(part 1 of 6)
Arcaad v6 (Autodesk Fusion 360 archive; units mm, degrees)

design "Arcaad" references "Joystick assembly", "Untitled", "Arcade_Box"
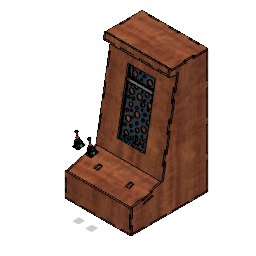
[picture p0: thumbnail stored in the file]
parameter "th" = 12
parameter "bl" = 480
parameter "bw" = 220
parameter "dbToolDia" = 6.35
parameter "dbOffset" = 0 comment "Do NOT change formula"
parameter "dbRadius" = 3.175 (= "( dbToolDia + dbOffset ) / 2") comment "Do NOT change formula"
parameter "dbHoleOffset" = 2.2451 (= "dbRadius / sqrt(2)") comment "Do NOT change formula"
component_insert "Component Insert1"
position "Position1"
sketch "Sketch1" plane through (0, 0, -312.3436) normal (0, 0, -1) x axis (-1, 0, 0)
  line L1 (205, -584.2019) -> (205, -596.2019)
  line L2 (300, -584.2019) -> (205, -584.2019)
  line L3 (300, -378.4667) -> (300, -584.2019)
  line L4 (294, -378.4667) -> (300, -378.4667)
  line L5 (294, -393.4667) -> (294, -378.4667)
  line L6 (288, -393.4667) -> (294, -393.4667)
  line L7 (288, -313.4667) -> (288, -393.4667)
  line L8 (294, -313.4667) -> (288, -313.4667)
  line L9 (294, -328.4667) -> (294, -313.4667)
  line L10 (300, -328.4667) -> (294, -328.4667)
  line L11 (300, -128.4667) -> (300, -328.4667)
  line L12 (294, -128.4667) -> (300, -128.4667)
  line L13 (294, -143.4667) -> (294, -128.4667)
  line L14 (288, -143.4667) -> (294, -143.4667)
  line L15 (288, -63.4667) -> (288, -143.4667)
  line L16 (294, -63.4667) -> (288, -63.4667)
  line L17 (294, -78.4667) -> (294, -63.4667)
  line L18 (300, -78.4667) -> (294, -78.4667)
  line L19 (300, 121.5333) -> (300, -78.4667)
  line L20 (294, 121.5333) -> (300, 121.5333)
  line L21 (294, 106.5333) -> (294, 121.5333)
  line L22 (288, 106.5333) -> (294, 106.5333)
  line L23 (288, 186.5333) -> (288, 106.5333)
  line L24 (294, 186.5333) -> (288, 186.5333)
  line L25 (294, 171.5333) -> (294, 186.5333)
  line L26 (300, 171.5333) -> (294, 171.5333)
  line L27 (300, 377.2686) -> (300, 171.5333)
  line L28 (205, 377.2686) -> (300, 377.2686)
  line L29 (205, 389.2686) -> (205, 377.2686)
  line L30 (155, 389.2686) -> (205, 389.2686)
  line L31 (155, 377.2686) -> (155, 389.2686)
  line L32 (25, 377.2686) -> (155, 377.2686)
  line L33 (25, 389.2686) -> (25, 377.2686)
  line L34 (-25, 389.2686) -> (25, 389.2686)
  line L35 (-25, 377.2686) -> (-25, 389.2686)
  line L36 (-155, 377.2686) -> (-25, 377.2686)
  line L37 (-155, 389.2686) -> (-155, 377.2686)
  line L38 (-205, 389.2686) -> (-155, 389.2686)
  line L39 (-205, 377.2686) -> (-205, 389.2686)
  line L40 (-300, 377.2686) -> (-205, 377.2686)
  line L41 (-300, 171.5333) -> (-300, 377.2686)
  line L42 (-294, 171.5333) -> (-300, 171.5333)
  line L43 (-294, 186.5333) -> (-294, 171.5333)
  line L44 (-288, 186.5333) -> (-294, 186.5333)
  line L45 (-288, 106.5333) -> (-288, 186.5333)
  line L46 (-294, 106.5333) -> (-288, 106.5333)
  line L47 (-294, 121.5333) -> (-294, 106.5333)
  line L48 (-300, 121.5333) -> (-294, 121.5333)
  line L49 (-300, -78.4667) -> (-300, 121.5333)
  line L50 (-294, -78.4667) -> (-300, -78.4667)
  line L51 (-294, -63.4667) -> (-294, -78.4667)
  line L52 (-288, -63.4667) -> (-294, -63.4667)
  line L53 (-288, -143.4667) -> (-288, -63.4667)
  line L54 (-294, -143.4667) -> (-288, -143.4667)
  line L55 (-294, -128.4667) -> (-294, -143.4667)
  line L56 (-300, -128.4667) -> (-294, -128.4667)
  line L57 (-300, -328.4667) -> (-300, -128.4667)
  line L58 (-294, -328.4667) -> (-300, -328.4667)
  line L59 (-294, -313.4667) -> (-294, -328.4667)
  line L60 (-288, -313.4667) -> (-294, -313.4667)
  line L61 (-288, -393.4667) -> (-288, -313.4667)
  line L62 (-294, -393.4667) -> (-288, -393.4667)
  line L63 (-294, -378.4667) -> (-294, -393.4667)
  line L64 (-300, -378.4667) -> (-294, -378.4667)
  line L65 (-300, -584.2019) -> (-300, -378.4667)
  line L66 (-205, -584.2019) -> (-300, -584.2019)
  line L67 (-205, -596.2019) -> (-205, -584.2019)
  line L68 (-155, -596.2019) -> (-205, -596.2019)
  line L69 (-155, -584.2019) -> (-155, -596.2019)
  line L70 (-25, -584.2019) -> (-155, -584.2019)
  line L71 (-25, -596.2019) -> (-25, -584.2019)
  line L72 (25, -596.2019) -> (-25, -596.2019)
  line L73 (25, -584.2019) -> (25, -596.2019)
  line L74 (155, -584.2019) -> (25, -584.2019)
  line L75 (155, -596.2019) -> (155, -584.2019)
  line L76 (205, -596.2019) -> (155, -596.2019)
  line L77 (205, 389.2686) -> (300, 389.2686)
  line L78 (205, 377.2686) -> (205, 389.2686)
  line L79 (300, 377.2686) -> (205, 377.2686)
  line L80 (300, 389.2686) -> (300, 377.2686)
  line L81 (25, 389.2686) -> (155, 389.2686)
  line L82 (-155, 389.2686) -> (-25, 389.2686)
  line L83 (-155, 377.2686) -> (-155, 389.2686)
  line L84 (-25, 377.2686) -> (-155, 377.2686)
  line L85 (-25, 389.2686) -> (-25, 377.2686)
  line L86 (-300, 389.2686) -> (-205, 389.2686)
  line L87 (-300, 377.2686) -> (-300, 389.2686)
  line L88 (-205, 377.2686) -> (-300, 377.2686)
  line L89 (-205, 389.2686) -> (-205, 377.2686)
  line L90 (-224, 171.5333) -> (-218, 171.5333)
  line L91 (-224, 121.5333) -> (-224, 171.5333)
  line L92 (-218, 121.5333) -> (-224, 121.5333)
  line L93 (-218, 106.5333) -> (-218, 121.5333)
  line L94 (-212, 106.5333) -> (-218, 106.5333)
  line L95 (-212, 186.5333) -> (-212, 106.5333)
  line L96 (-218, 186.5333) -> (-212, 186.5333)
  line L97 (-218, 171.5333) -> (-218, 186.5333)
  line L98 (300, 121.5333) -> (294, 121.5333)
  line L99 (300, 171.5333) -> (300, 121.5333)
  line L100 (294, 171.5333) -> (300, 171.5333)
  line L101 (294, 186.5333) -> (294, 171.5333)
  line L102 (288, 186.5333) -> (294, 186.5333)
  line L103 (288, 106.5333) -> (288, 186.5333)
  line L104 (294, 106.5333) -> (288, 106.5333)
  line L105 (294, 121.5333) -> (294, 106.5333)
  line L106 (-224, -78.4667) -> (-218, -78.4667)
  line L107 (-224, -128.4667) -> (-224, -78.4667)
  line L108 (-218, -128.4667) -> (-224, -128.4667)
  line L109 (-218, -143.4667) -> (-218, -128.4667)
  line L110 (-212, -143.4667) -> (-218, -143.4667)
  line L111 (-212, -63.4667) -> (-212, -143.4667)
  line L112 (-218, -63.4667) -> (-212, -63.4667)
  line L113 (-218, -78.4667) -> (-218, -63.4667)
  line L114 (-205, -596.2019) -> (-300, -596.2019)
  line L115 (-205, -584.2019) -> (-205, -596.2019)
  line L116 (-300, -584.2019) -> (-205, -584.2019)
  line L117 (-300, -596.2019) -> (-300, -584.2019)
  line L118 (-25, -596.2019) -> (-155, -596.2019)
  line L119 (-25, -584.2019) -> (-25, -596.2019)
  line L120 (-155, -584.2019) -> (-25, -584.2019)
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  point P135 (300, -596.2019)
  point P166 (300, -596.2019)
  point P159 (-224, -328.4667)
  point P164 (-224, -328.4667)
  point P78 (300, 389.2686)
  point P169 (300, 389.2686)
  coincident P135 P166
  coincident P159 P164
  coincident P78 P169
extrude "Extrude1" new body sketch "Sketch1" to an object
position "Position2"
position "Position3"
combine "Combine1"
sketch "Sketch2" plane through (0, -584.2019, 0) normal (0, -1, 0) x axis (1, 0, 0)
  line L1 (-300, 287.6564) -> (-288, 287.6564)
  line L2 (-300, 193.6564) -> (-300, 287.6564)
  line L3 (-294, 193.6564) -> (-300, 193.6564)
  line L4 (-294, 208.6564) -> (-294, 193.6564)
  line L5 (-288, 208.6564) -> (-294, 208.6564)
  line L6 (-288, 287.6564) -> (-288, 208.6564)
  line L7 (223.5439, 299.6564) -> (-300, 299.6564)
  line L8 (223.5439, -312.3436) -> (223.5439, 299.6564)
  line L9 (-300, -312.3436) -> (223.5439, -312.3436)
  line L10 (-300, 299.6564) -> (-300, -312.3436)
  line L11 (-300, -312.3436) -> (224, -312.3436)
  line L12 (-288, -300.3436) -> (211.5439, -300.3436)
  line L13 (-288, 287.6564) -> (-288, -300.3436)
  line L14 (211.5439, 287.6564) -> (-288, 287.6564)
  line L15 (211.5439, -300.3436) -> (211.5439, 287.6564)
  line L16 (-38, -312.3436) -> (-38.228, 299.6564)
  line L17 (-78, -312.3585) -> (-78.228, 299.6415)
  line L18 (2, -312.3287) -> (1.772, 299.6713)
  line L19 (-13, -312.3343) -> (-13.228, 299.6657)
  line L20 (-63, -312.3529) -> (-63.228, 299.6471)
  line L21 (-223, -312.3529) -> (-223.228, 299.6471)
  line L22 (-238, -312.3585) -> (-238.228, 299.6415)
  line L23 (-173, -312.3343) -> (-173.228, 299.6657)
  line L24 (-158, -312.3287) -> (-158.228, 299.6713)
  line L25 (97, -312.3529) -> (96.772, 299.6471)
  line L26 (82, -312.3585) -> (81.772, 299.6415)
  line L27 (147, -312.3343) -> (146.772, 299.6657)
  line L28 (162, -312.3287) -> (161.772, 299.6713)
  line L29 (-294, -306.3436) -> (217.5439, -306.3436)
  line L30 (-294, 293.6564) -> (-294, -306.3436)
  line L31 (217.5439, 293.6564) -> (-294, 293.6564)
  line L32 (217.5439, -306.3436) -> (217.5439, 293.6564)
  line L33 (224, -312.3436) -> (-300, -312.3436)
  line L34 (-173.0022, -312.3529) -> (-223, -312.3529)
  line L35 (-173.0022, -306.3436) -> (-173.0022, -312.3529)
  line L36 (-223, -306.3436) -> (-173.0022, -306.3436)
  line L37 (-223, -312.3529) -> (-223, -306.3436)
  line L38 (-63.0022, -312.3343) -> (-13, -312.3343)
  line L39 (-63.0022, -306.3436) -> (-63.0022, -312.3343)
  line L40 (-13, -306.3436) -> (-63.0022, -306.3436)
  line L41 (-13, -312.3343) -> (-13, -306.3436)
  line L42 (146.9978, -312.3529) -> (97, -312.3529)
  line L43 (146.9978, -306.3436) -> (146.9978, -312.3529)
  line L44 (97, -306.3436) -> (146.9978, -306.3436)
  line L45 (97, -312.3529) -> (97, -306.3436)
  line L46 (146.772, 293.6564) -> (96.7742, 293.6564)
  line L47 (146.772, 299.6657) -> (146.772, 293.6564)
  line L48 (96.7742, 299.6657) -> (146.772, 299.6657)
  line L49 (96.7742, 293.6564) -> (96.7742, 299.6657)
  line L50 (-13.228, 293.6564) -> (-63.2258, 293.6564)
  line L51 (-13.228, 299.6657) -> (-13.228, 293.6564)
  line L52 (-63.2258, 299.6657) -> (-13.228, 299.6657)
  line L53 (-63.2258, 293.6564) -> (-63.2258, 299.6657)
  line L54 (-173.228, 293.6564) -> (-223.2258, 293.6564)
  line L55 (-173.228, 299.6657) -> (-173.228, 293.6564)
  line L56 (-223.2258, 299.6657) -> (-173.228, 299.6657)
  line L57 (-223.2258, 293.6564) -> (-223.2258, 299.6657)
  point P10 (223.5439, -312.3436)
  point P8 (-300, 299.6564)
  point P12 (-300, 299.6564)
  point P19 (-38.228, 299.6564)
  point P20 (-38, -312.3436)
  point P13 (224, -312.3436)
  point P49 (224, -312.3436)
  point P51 (-173.0022, -306.3436)
  point P54 (-63.0022, -306.3436)
  point P57 (146.9978, -306.3436)
  point P59 (96.7742, 293.6564)
  point P62 (-63.2258, 293.6564)
  point P65 (-223.2258, 293.6564)
  horizontal L7
  vertical L8
  horizontal L9
  vertical L10
  coincident P10 L11
  coincident P8 P12
  midpoint L7 P19
  midpoint L11 P20
  coincident P13 P49
  horizontal L34
  vertical L35
  horizontal L36
  vertical L37
  coincident L29 P51
  coincident L23 P51
  horizontal L38
  vertical L39
  horizontal L40
  vertical L41
  coincident L29 P54
  coincident L20 P54
  horizontal L42
  vertical L43
  horizontal L44
  vertical L45
  coincident L27 P57
  coincident L29 P57
  horizontal L46
  vertical L47
  horizontal L48
  vertical L49
  coincident L31 P59
  coincident L25 P59
  horizontal L50
  vertical L51
  horizontal L52
  vertical L53
  coincident L31 P62
  coincident L20 P62
  horizontal L54
  vertical L55
  horizontal L56
  vertical L57
  coincident L21 P65
  coincident L31 P65
  dimension "d6" = 12
  dimension "d7" = 40
  dimension "d8" = -40
  dimension "d9" = -25
  dimension "d10" = 25
  dimension "d15" = 6
  dimension "d13" R-Pattern1-uDistance = 160
  dimension "d14" R-Pattern1-vDistance = 0
position "Position4"
extrude "Extrude1" new body sketch "Sketch2" profile of L1 L2 L3 L4 L5 L6 L7 L8 L9 L10 L11 L12 L14 L13 L15 L16 L17 L18 L19 L20 L21 L22 L23 L24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 to an object
extrude "Extrude2" cut of existing geometry blind -10
extrude "Extrude3" cut of existing geometry blind -10
extrude "Extrude4" cut of existing geometry blind -13
combine "Combine2"
sketch "Sketch3" plane through (0, -596.2019, 0) normal (0, -1, 0) x axis (1, 0, 0)
  line L1 (-63, -312.3343) -> (-63, -312.3436)
  line L2 (-63.0022, -306.3436) -> (-63, -312.3343)
  line L3 (-78.0022, -306.3436) -> (-63.0022, -306.3436)
  line L4 (-78.0045, -300.3436) -> (-78.0022, -306.3436)
  line L5 (1.9955, -300.3436) -> (-78.0045, -300.3436)
  line L6 (1.9978, -306.3436) -> (1.9955, -300.3436)
  line L7 (-13.0022, -306.3436) -> (1.9978, -306.3436)
  line L8 (-13, -312.3343) -> (-13.0022, -306.3436)
  line L9 (-13, -312.3436) -> (-13, -312.3343)
  line L10 (97, -312.3436) -> (-13, -312.3436)
  line L11 (97, -306.3436) -> (97, -312.3436)
  line L12 (81.9978, -306.3436) -> (97, -306.3436)
  line L13 (81.9955, -300.3436) -> (81.9978, -306.3436)
  line L14 (161.9955, -300.3436) -> (81.9955, -300.3436)
  line L15 (161.9978, -306.3436) -> (161.9955, -300.3436)
  line L16 (146.9978, -306.3436) -> (161.9978, -306.3436)
  line L17 (146.9978, -312.3436) -> (146.9978, -306.3436)
  line L18 (223.5439, -312.3436) -> (146.9978, -312.3436)
  line L19 (223.5439, 299.6564) -> (223.5439, -312.3436)
  line L20 (146.772, 299.6564) -> (223.5439, 299.6564)
  line L21 (146.7742, 293.6564) -> (146.772, 299.6564)
  line L22 (161.7742, 293.6564) -> (146.7742, 293.6564)
  line L23 (161.7764, 287.6564) -> (161.7742, 293.6564)
  line L24 (81.7764, 287.6564) -> (161.7764, 287.6564)
  line L25 (81.7742, 293.6564) -> (81.7764, 287.6564)
  line L26 (96.7742, 293.6564) -> (81.7742, 293.6564)
  line L27 (96.7742, 299.6564) -> (96.7742, 293.6564)
  line L28 (-13.228, 299.6564) -> (96.7742, 299.6564)
  line L29 (-13.228, 293.6564) -> (-13.228, 299.6564)
  line L30 (1.7742, 293.6564) -> (-13.228, 293.6564)
  line L31 (1.7764, 287.6564) -> (1.7742, 293.6564)
  line L32 (-78.2236, 287.6564) -> (1.7764, 287.6564)
  line L33 (-78.2258, 293.6564) -> (-78.2236, 287.6564)
  line L34 (-63.2258, 293.6564) -> (-78.2258, 293.6564)
  line L35 (-63.2258, 299.6564) -> (-63.2258, 293.6564)
  line L36 (-173.228, 299.6564) -> (-63.2258, 299.6564)
  line L37 (-173.228, 293.6564) -> (-173.228, 299.6564)
  line L38 (-158.2258, 293.6564) -> (-173.228, 293.6564)
  line L39 (-158.2236, 287.6564) -> (-158.2258, 293.6564)
  line L40 (-238.2236, 287.6564) -> (-158.2236, 287.6564)
  line L41 (-238.2258, 293.6564) -> (-238.2236, 287.6564)
  line L42 (-223.2258, 293.6564) -> (-238.2258, 293.6564)
  line L43 (-223.2258, 299.6564) -> (-223.2258, 293.6564)
  line L44 (-300, 299.6564) -> (-223.2258, 299.6564)
  line L45 (-300, -312.3436) -> (-300, 299.6564)
  line L46 (-223, -312.3436) -> (-300, -312.3436)
  line L47 (-223, -306.3436) -> (-223, -312.3436)
  line L48 (-238.0022, -306.3436) -> (-223, -306.3436)
  line L49 (-238.0045, -300.3436) -> (-238.0022, -306.3436)
  line L50 (-158.0045, -300.3436) -> (-238.0045, -300.3436)
  line L51 (-158.0022, -306.3436) -> (-158.0045, -300.3436)
  line L52 (-173.0022, -306.3436) -> (-158.0022, -306.3436)
  line L53 (-173.0022, -312.3436) -> (-173.0022, -306.3436)
  line L54 (-63, -312.3436) -> (-173.0022, -312.3436)
  line L55 (224, 299.6564) -> (-300, 299.6564)
  line L56 (224, 287.6564) -> (224, 299.6564)
  line L57 (-300, 287.6564) -> (224, 287.6564)
  line L58 (-300, 299.6564) -> (-300, 287.6564)
  point P58 (224, 287.6564)
  point P60 (224, 287.6564)
  point P46 (-300, 299.6564)
  point P56 (-300, 299.6564)
  horizontal L55
  vertical L56
  horizontal L57
  vertical L58
  coincident P58 P60
  coincident P46 P56
extrude "Extrude1" new body sketch "Sketch3" profile of L19 L20 L21 L22 L23 L24 L25 L26 L27 L28 L29 L30 L31 L32 L33 L34 L35 L36 L37 L38 L39 L40 L41 L42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 to an object OffsetX 0 OffsetY 0 OffsetZ 0 AngleZ 0
combine "Combine1"
sketch "Sketch4" plane through (0, 389.2686, 0) normal (0, 1, 0) x axis (-1, 0, 0)
  line L1 (-224, -300.3436) -> (300, -300.3436)
  line L2 (-224, -312.3436) -> (-224, -300.3436)
  line L3 (300, -312.3436) -> (-224, -312.3436)
  line L4 (300, -300.3436) -> (300, -312.3436)
  line L5 (173.0022, -306.3436) -> (173.0022, -312.3436)
  line L6 (158.0022, -306.3436) -> (173.0022, -306.3436)
  line L7 (158.0045, -300.3436) -> (158.0022, -306.3436)
  line L8 (238.0045, -300.3436) -> (158.0045, -300.3436)
  line L9 (238.0022, -306.3436) -> (238.0045, -300.3436)
  line L10 (223, -306.3436) -> (238.0022, -306.3436)
  line L11 (223, -312.3436) -> (223, -306.3436)
  line L12 (173.0022, -312.3436) -> (223, -312.3436)
  line L13 (63, -312.3436) -> (63, -312.3343)
  line L14 (13, -312.3436) -> (63, -312.3436)
  line L15 (13, -312.3343) -> (13, -312.3436)
  line L16 (13.0022, -306.3436) -> (13, -312.3343)
  line L17 (-1.9978, -306.3436) -> (13.0022, -306.3436)
  line L18 (-1.9955, -300.3436) -> (-1.9978, -306.3436)
  line L19 (78.0045, -300.3436) -> (-1.9955, -300.3436)
  line L20 (78.0022, -306.3436) -> (78.0045, -300.3436)
  line L21 (63.0022, -306.3436) -> (78.0022, -306.3436)
  line L22 (63, -312.3343) -> (63.0022, -306.3436)
  line L23 (-97, -312.3436) -> (-97, -306.3436)
  line L24 (-146.9978, -312.3436) -> (-97, -312.3436)
  line L25 (-146.9978, -306.3436) -> (-146.9978, -312.3436)
  line L26 (-161.9978, -306.3436) -> (-146.9978, -306.3436)
  line L27 (-161.9955, -300.3436) -> (-161.9978, -306.3436)
  line L28 (-81.9955, -300.3436) -> (-161.9955, -300.3436)
  line L29 (-81.9978, -306.3436) -> (-81.9955, -300.3436)
  line L30 (-97, -306.3436) -> (-81.9978, -306.3436)
extrude "Extrude2" cut sketch "Sketch4" profile of L1 L2 L3 L4 L5 L6 L7 L9 L10 L11 L13 L15 L16 L17 L18 L20 L21 L22 L23 L25 L26 L27 L29 L30 against normal blind 12
sketch "Sketch5" plane through (0, 377.2686, 0) normal (0, 1, 0) x axis (-1, 0, 0)
  line L1 (288, -127.9218) -> (288, -23.4999)
  line L2 (294, -127.9218) -> (288, -127.9218)
  line L3 (294, -142.9218) -> (294, -127.9218)
  line L4 (300, -142.9218) -> (294, -142.9218)
  line L5 (300, -23.4999) -> (300, -142.9218)
  line L6 (288, -23.4999) -> (300, -23.4999)
  line L7 (-212, -23.4999) -> (-212, -127.9218)
  line L8 (-224, -23.4999) -> (-212, -23.4999)
  line L9 (-224, -142.9218) -> (-224, -23.4999)
  line L10 (-218, -142.9218) -> (-224, -142.9218)
  line L11 (-218, -127.9218) -> (-218, -142.9218)
  line L12 (-212, -127.9218) -> (-218, -127.9218)
  line L13 (-224, -142.9218) -> (-218, -142.9218)
  line L14 (-224, -192.9218) -> (-224, -142.9218)
  line L15 (-218, -192.9218) -> (-224, -192.9218)
  line L16 (-218, -207.9218) -> (-218, -192.9218)
  line L17 (-212, -207.9218) -> (-218, -207.9218)
  line L18 (-212, -127.9218) -> (-212, -207.9218)
  line L19 (-218, -127.9218) -> (-212, -127.9218)
  line L20 (-218, -142.9218) -> (-218, -127.9218)
  line L21 (-212, -300.3436) -> (-224, -300.3436)
  line L22 (-212, -207.9218) -> (-212, -300.3436)
  line L23 (-218, -207.9218) -> (-212, -207.9218)
  line L24 (-218, -192.9218) -> (-218, -207.9218)
  line L25 (-224, -192.9218) -> (-218, -192.9218)
  line L26 (-224, -300.3436) -> (-224, -192.9218)
  line L27 (288, -300.3436) -> (288, -207.9218)
  line L28 (300, -300.3436) -> (288, -300.3436)
  line L29 (300, -192.9218) -> (300, -300.3436)
  line L30 (294, -192.9218) -> (300, -192.9218)
  line L31 (294, -207.9218) -> (294, -192.9218)
  line L32 (288, -207.9218) -> (294, -207.9218)
  line L33 (294, -142.9218) -> (300, -142.9218)
  line L34 (294, -127.9218) -> (294, -142.9218)
  line L35 (288, -127.9218) -> (294, -127.9218)
  line L36 (288, -207.9218) -> (288, -127.9218)
  line L37 (294, -207.9218) -> (288, -207.9218)
  line L38 (294, -192.9218) -> (294, -207.9218)
  line L39 (300, -192.9218) -> (294, -192.9218)
  line L40 (300, -142.9218) -> (300, -192.9218)
  line L41 (63, -312.3436) -> (63, -312.3343)
  line L42 (173.0022, -312.3436) -> (63, -312.3436)
  line L43 (173.0022, -306.3436) -> (173.0022, -312.3436)
  line L44 (158.0022, -306.3436) -> (173.0022, -306.3436)
  line L45 (158.0045, -300.3436) -> (158.0022, -306.3436)
  line L46 (238.0045, -300.3436) -> (158.0045, -300.3436)
  line L47 (238.0022, -306.3436) -> (238.0045, -300.3436)
  line L48 (223, -306.3436) -> (238.0022, -306.3436)
  line L49 (223, -312.3436) -> (223, -306.3436)
  line L50 (300, -312.3436) -> (223, -312.3436)
  line L51 (300, 299.6564) -> (300, -312.3436)
  line L52 (223.2258, 299.6564) -> (300, 299.6564)
  line L53 (223.2258, 293.6564) -> (223.2258, 299.6564)
  line L54 (238.2258, 293.6564) -> (223.2258, 293.6564)
  line L55 (238.2236, 287.6564) -> (238.2258, 293.6564)
  line L56 (158.2236, 287.6564) -> (238.2236, 287.6564)
  line L57 (158.2258, 293.6564) -> (158.2236, 287.6564)
  line L58 (173.228, 293.6564) -> (158.2258, 293.6564)
  line L59 (173.228, 299.6564) -> (173.228, 293.6564)
  line L60 (63.2258, 299.6564) -> (173.228, 299.6564)
  line L61 (63.2258, 293.6564) -> (63.2258, 299.6564)
  line L62 (78.2258, 293.6564) -> (63.2258, 293.6564)
  line L63 (78.2236, 287.6564) -> (78.2258, 293.6564)
  line L64 (-1.7764, 287.6564) -> (78.2236, 287.6564)
  line L65 (-1.7742, 293.6564) -> (-1.7764, 287.6564)
  line L66 (13.228, 293.6564) -> (-1.7742, 293.6564)
  line L67 (13.228, 299.6564) -> (13.228, 293.6564)
  line L68 (-96.7742, 299.6564) -> (13.228, 299.6564)
  line L69 (-96.7742, 293.6564) -> (-96.7742, 299.6564)
  line L70 (-81.7742, 293.6564) -> (-96.7742, 293.6564)
  line L71 (-81.7764, 287.6564) -> (-81.7742, 293.6564)
  line L72 (-161.7764, 287.6564) -> (-81.7764, 287.6564)
  line L73 (-161.7742, 293.6564) -> (-161.7764, 287.6564)
  line L74 (-146.7742, 293.6564) -> (-161.7742, 293.6564)
  line L75 (-146.772, 299.6564) -> (-146.7742, 293.6564)
  line L76 (-223.5439, 299.6564) -> (-146.772, 299.6564)
  line L77 (-223.5439, -312.3436) -> (-223.5439, 299.6564)
  line L78 (-146.9978, -312.3436) -> (-223.5439, -312.3436)
  line L79 (-146.9978, -306.3436) -> (-146.9978, -312.3436)
  line L80 (-161.9978, -306.3436) -> (-146.9978, -306.3436)
  line L81 (-161.9955, -300.3436) -> (-161.9978, -306.3436)
  line L82 (-81.9955, -300.3436) -> (-161.9955, -300.3436)
  line L83 (-81.9978, -306.3436) -> (-81.9955, -300.3436)
  line L84 (-97, -306.3436) -> (-81.9978, -306.3436)
  line L85 (-97, -312.3436) -> (-97, -306.3436)
  line L86 (13, -312.3436) -> (-97, -312.3436)
  line L87 (13, -312.3343) -> (13, -312.3436)
  line L88 (13.0022, -306.3436) -> (13, -312.3343)
  line L89 (-1.9978, -306.3436) -> (13.0022, -306.3436)
  line L90 (-1.9955, -300.3436) -> (-1.9978, -306.3436)
  line L91 (78.0045, -300.3436) -> (-1.9955, -300.3436)
  line L92 (78.0022, -306.3436) -> (78.0045, -300.3436)
  line L93 (63.0022, -306.3436) -> (78.0022, -306.3436)
  line L94 (63, -312.3343) -> (63.0022, -306.3436)
  line L95 (300, -23.4999) -> (-224, -23.4999)
  point P10 (-224, -23.4999)
  point P96 (-224, -23.4999)
  point P7 (300, -23.4999)
  point P97 (300, -23.4999)
  coincident P10 P96
  coincident P7 P97
extrude "Extrude1" new body sketch "Sketch5" profile of L1 L2 L3 L4 L5 L6 L7 L8 L10 L11 L12 L13 L15 L16 L17 L18 L19 L20 L21 L22 L23 L24 L25 L27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 to an object
position "Position5"
sketch "Sketch6" plane through (0, -3.047, -17.2805) normal (0, 0.1736, 0.9848) x axis (1, 0, 0)
  line L1 (-288, 349.4354) -> (-288, 249.4354)
  line L2 (-300, 349.4354) -> (-288, 349.4354)
  line L3 (-300, 224.4354) -> (-300, 349.4354)
  line L4 (-294, 224.4354) -> (-300, 224.4354)
  line L5 (-294, 249.4354) -> (-294, 224.4354)
  line L6 (-288, 249.4354) -> (-294, 249.4354)
  line L7 (224, 349.4354) -> (-300, 349.4354)
  line L8 (224, -350.5) -> (224, 349.4354)
  line L9 (-300, -350.5) -> (224, -350.5)
  line L10 (-300, 349.4354) -> (-300, -350.5)
  line L11 (-288, 337.4354) -> (-288, -338.5)
  line L12 (212, 337.4354) -> (-288, 337.4354)
  line L13 (212, -338.5) -> (212, 337.4354)
  line L14 (-288, -338.5) -> (212, -338.5)
  line L15 (-38, -350.5) -> (-38, 349.4354)
  line L16 (212, -0.5323) -> (-288, -0.5323)
  line L17 (-148, 239.4677) -> (72, 239.4677)
  line L18 (-148, -240.5323) -> (-148, 239.4677)
  line L19 (72, -240.5323) -> (-148, -240.5323)
  line L20 (72, 239.4677) -> (72, -240.5323)
  line L21 (-148, -240.5323) -> (72, 239.4677)
  line L22 (72, -240.5323) -> (-148, 239.4677)
  point P4 (-300, 349.4354)
  point P8 (-300, 349.4354)
  point P16 (-38, 349.4354)
  point P17 (-38, -350.5)
  point P18 (-288, -0.5323)
  point P19 (212, -0.5323)
  point P24 (-38, -0.5323)
  point P21 (-148, 239.4677)
  point P22 (-148, -240.5323)
  point P23 (72, -240.5323)
  horizontal L7
  vertical L8
  horizontal L9
  vertical L10
  coincident P4 P8
  midpoint L7 P16
  midpoint L9 P17
  midpoint L11 P18
  midpoint L13 P19
  perpendicular L13 L16
  perpendicular L17 L18
  parallel L17 L19
  parallel L18 L20
  horizontal L17
  coincident L21 P24
  coincident L22 P24
  midpoint L15 P24
  dimension "d31" = 12
  dimension "d32" distance P21 P22 = 480 (= "bl")
  dimension "d33" distance P22 P23 = 220 (= "bw")
extrude "Extrude1" new body sketch "Sketch6" profile of L1 L2 L3 L4 L5 L6 L7 L8 L9 L10 L11 L12 L13 L14 L15 L16 L17 L18 L19 L20 to an object
combine "Combine1"
sketch "Sketch7" plane through (0, -320.5052, -86.2522) normal (0, 0.9656, 0.2599) x axis (1, 0, 0)
  line L1 (-288, -223.7285) -> (-288, -303.7285)
  line L2 (-300, -223.7285) -> (-288, -223.7285)
  line L3 (-300, -303.7285) -> (-300, -223.7285)
  line L4 (-288, -303.7285) -> (-300, -303.7285)
  line L5 (224, -143.475) -> (-300, -143.475)
  line L6 (224, -383.9821) -> (224, -143.475)
  line L7 (-300, -383.9821) -> (224, -383.9821)
  line L8 (-300, -143.475) -> (-300, -383.9821)
  line L9 (-288, -233.7285) -> (-300, -233.7285)
  line L10 (-288, -143.475) -> (-288, -233.7285)
  line L11 (-300, -143.475) -> (-288, -143.475)
  line L12 (-300, -233.7285) -> (-300, -143.475)
  line L13 (-300, -293.7285) -> (-288, -293.7285)
  line L14 (-300, -383.9821) -> (-300, -293.7285)
  line L15 (-288, -383.9821) -> (-300, -383.9821)
  line L16 (-288, -293.7285) -> (-288, -383.9821)
  line L17 (224, -233.7285) -> (212, -233.7285)
  line L18 (224, -143.475) -> (224, -233.7285)
  line L19 (212, -143.475) -> (224, -143.475)
  line L20 (212, -233.7285) -> (212, -143.475)
  line L21 (212, -303.7285) -> (212, -223.7285)
  line L22 (224, -303.7285) -> (212, -303.7285)
  line L23 (224, -223.7285) -> (224, -303.7285)
  line L24 (212, -223.7285) -> (224, -223.7285)
  line L25 (212, -293.7285) -> (224, -293.7285)
  line L26 (212, -383.9821) -> (212, -293.7285)
  line L27 (224, -383.9821) -> (212, -383.9821)
  line L28 (224, -293.7285) -> (224, -383.9821)
  point P8 (224, -383.9821)
  point P11 (224, -383.9821)
  point P6 (-300, -143.475)
  point P10 (-300, -143.475)
  horizontal L5
  vertical L6
  horizontal L7
  vertical L8
  coincident P8 P11
  coincident P6 P10
extrude "Extrude1" new body sketch "Sketch7" along normal blind 12
combine "Combine1"
copy_paste "CopyPaste1"
sketch "Sketch8" plane through (0, -0.9632, -5.4629) normal (0, 0.1736, 0.9848) x axis (1, 0, 0)
  line L1 (72, 239.4677) -> (-148, 239.4677)
  line L2 (72, -240.5323) -> (72, 239.4677)
  line L3 (-148, -240.5323) -> (72, -240.5323)
  line L4 (-148, 239.4677) -> (-148, -240.5323)
  line L5 (224, 349.4354) -> (224, 337.4354)
  line L6 (-300, 349.4354) -> (224, 349.4354)
  line L7 (-300, 224.4354) -> (-300, 349.4354)
  line L8 (-294, 224.4354) -> (-300, 224.4354)
  line L9 (-294, 249.4354) -> (-294, 224.4354)
  line L10 (-288, 249.4354) -> (-294, 249.4354)
  line L11 (-288, 149.4354) -> (-288, 249.4354)
  line L12 (-294, 149.4354) -> (-288, 149.4354)
  line L13 (-294, 174.4354) -> (-294, 149.4354)
  line L14 (-300, 174.4354) -> (-294, 174.4354)
  line L15 (-300, 24.4354) -> (-300, 174.4354)
  line L16 (-294, 24.4354) -> (-300, 24.4354)
  line L17 (-294, 49.4354) -> (-294, 24.4354)
  line L18 (-288, 49.4354) -> (-294, 49.4354)
  line L19 (-288, -50.5646) -> (-288, 49.4354)
  line L20 (-294, -50.5646) -> (-288, -50.5646)
  line L21 (-294, -25.5646) -> (-294, -50.5646)
  line L22 (-300, -25.5646) -> (-294, -25.5646)
  line L23 (-300, -175.5646) -> (-300, -25.5646)
  line L24 (-294, -175.5646) -> (-300, -175.5646)
  line L25 (-294, -150.5646) -> (-294, -175.5646)
  line L26 (-288, -150.5646) -> (-294, -150.5646)
  line L27 (-288, -250.5646) -> (-288, -150.5646)
  line L28 (-294, -250.5646) -> (-288, -250.5646)
  line L29 (-294, -225.5646) -> (-294, -250.5646)
  line L30 (-300, -225.5646) -> (-294, -225.5646)
  line L31 (-300, -350.5) -> (-300, -225.5646)
  line L32 (224, -350.5) -> (-300, -350.5)
  line L33 (224, -225.5646) -> (224, -350.5)
  line L34 (218, -225.5646) -> (224, -225.5646)
  line L35 (218, -250.5646) -> (218, -225.5646)
  line L36 (212, -250.5646) -> (218, -250.5646)
  line L37 (212, -150.5646) -> (212, -250.5646)
  line L38 (218, -150.5646) -> (212, -150.5646)
  line L39 (218, -175.5646) -> (218, -150.5646)
  line L40 (224, -175.5646) -> (218, -175.5646)
  line L41 (224, -25.5646) -> (224, -175.5646)
  line L42 (218, -25.5646) -> (224, -25.5646)
  line L43 (218, -50.5646) -> (218, -25.5646)
  line L44 (212, -50.5646) -> (218, -50.5646)
  line L45 (212, 49.4354) -> (212, -50.5646)
  line L46 (218, 49.4354) -> (212, 49.4354)
  line L47 (218, 24.4354) -> (218, 49.4354)
  line L48 (224, 24.4354) -> (218, 24.4354)
  line L49 (224, 174.4354) -> (224, 24.4354)
  line L50 (218, 174.4354) -> (224, 174.4354)
  line L51 (218, 149.4354) -> (218, 174.4354)
  line L52 (212, 149.4354) -> (218, 149.4354)
  line L53 (212, 249.4354) -> (212, 149.4354)
  line L54 (218, 249.4354) -> (212, 249.4354)
  line L55 (218, 224.4354) -> (218, 249.4354)
  line L56 (224, 224.4354) -> (218, 224.4354)
  line L57 (224, 337.4354) -> (224, 224.4354)
  line L58 (212, 349.4354) -> (-288, 349.4354)
  line L59 (212, 337.4354) -> (212, 349.4354)
  line L60 (-288, 337.4354) -> (212, 337.4354)
  line L61 (-288, 349.4354) -> (-288, 337.4354)
  line L62 (-38, 337.4354) -> (-38, 349.4354)
  line L63 (212, 343.4354) -> (-288, 343.4354)
  line L64 (-78, 337.4354) -> (-78, 349.4354)
  line L65 (2, 337.4354) -> (2, 349.4354)
  line L66 (-13, 337.4354) -> (-13, 349.4354)
  line L67 (-63, 337.4354) -> (-63, 349.4354)
  line L68 (-218, 337.4354) -> (-218, 349.4354)
  line L69 (-203, 337.4354) -> (-203, 349.4354)
  line L70 (-178, 337.4354) -> (-178, 349.4354)
  line L71 (-153, 337.4354) -> (-153, 349.4354)
  line L72 (-138, 337.4354) -> (-138, 349.4354)
  line L73 (62, 337.4354) -> (62, 349.4354)
  line L74 (77, 337.4354) -> (77, 349.4354)
  line L75 (102, 337.4354) -> (102, 349.4354)
  line L76 (127, 337.4354) -> (127, 349.4354)
  line L77 (142, 337.4354) -> (142, 349.4354)
  point P67 (212, 337.4354)
  point P70 (212, 337.4354)
  point P65 (-288, 349.4354)
  point P69 (-288, 349.4354)
  point P71 (-38, 349.4354)
  point P72 (-38, 337.4354)
  horizontal L58
  vertical L59
  horizontal L60
  vertical L61
  coincident P67 P70
  coincident P65 P69
  midpoint L58 P71
  midpoint L60 P72
  dimension "d38" = 6
  dimension "d39" = 40
  dimension "d40" = -40
  dimension "d41" = -25
  dimension "d42" = 25
  dimension "d45" R-Pattern1-uDistance = 140
  dimension "d46" R-Pattern1-vDistance = 0
extrude "Extrude1" new body sketch "Sketch8" profile of L6 L58 L59 L60 L61 L62 L63 L64 L65 L66 L67 L68 L69 L70 L71 L72 L73 L74 L75 L76 L77 to an object
extrude "Extrude2" add sketch "Sketch8" profile of L6 L58 L60 L62 L63 L64 L65 L66 L67 L68 L69 L70 L71 L72 L73 L74 L75 L76 L77 no distance stored
combine "Combine2"
sketch "Sketch13" plane through (224, 0, 0) normal (1, 0, 0) x axis (0, 0, -1)
  line L1 (156.3436, -596.2019) -> (156.3436, -584.2019)
  line L2 (206.3436, -596.2019) -> (156.3436, -596.2019)
  line L3 (206.3436, -584.2019) -> (206.3436, -596.2019)
  line L4 (300.3436, -584.2019) -> (206.3436, -584.2019)
  line L5 (300.3436, -378.4667) -> (300.3436, -584.2019)
  line L6 (312.3436, -378.4667) -> (300.3436, -378.4667)
  line L7 (312.3436, -328.4667) -> (312.3436, -378.4667)
  line L8 (300.3436, -328.4667) -> (312.3436, -328.4667)
  line L9 (300.3436, -128.4667) -> (300.3436, -328.4667)
  line L10 (312.3436, -128.4667) -> (300.3436, -128.4667)
  line L11 (312.3436, -78.4667) -> (312.3436, -128.4667)
  line L12 (300.3436, -78.4667) -> (312.3436, -78.4667)
  line L13 (300.3436, 121.5333) -> (300.3436, -78.4667)
  line L14 (312.3436, 121.5333) -> (300.3436, 121.5333)
  line L15 (312.3436, 171.5333) -> (312.3436, 121.5333)
  line L16 (300.3436, 171.5333) -> (312.3436, 171.5333)
  line L17 (300.3436, 377.2686) -> (300.3436, 171.5333)
  line L18 (192.9218, 377.2686) -> (300.3436, 377.2686)
  line L19 (192.9218, 389.2686) -> (192.9218, 377.2686)
  line L20 (142.9218, 389.2686) -> (192.9218, 389.2686)
  line L21 (142.9218, 377.2686) -> (142.9218, 389.2686)
  line L22 (23.4999, 377.2686) -> (142.9218, 377.2686)
  line L23 (23.4999, 389.2686) -> (23.4999, 377.2686)
  line L24 (11.6822, 391.3524) -> (23.4999, 389.2686)
  line L25 (2.9998, 342.112) -> (11.6822, 391.3524)
  line L26 (64.0579, 331.3458) -> (2.9998, 342.112)
  line L27 (66.1417, 343.1635) -> (64.0579, 331.3458)
  line L28 (77.9594, 341.0797) -> (66.1417, 343.1635)
  line L29 (56.2534, 217.9787) -> (77.9594, 341.0797)
  line L30 (44.4357, 220.0625) -> (56.2534, 217.9787)
  line L31 (35.7532, 170.8221) -> (44.4357, 220.0625)
  line L32 (47.5709, 168.7384) -> (35.7532, 170.8221)
  line L33 (21.5237, 21.0172) -> (47.5709, 168.7384)
  line L34 (9.706, 23.101) -> (21.5237, 21.0172)
  line L35 (1.0236, -26.1394) -> (9.706, 23.101)
  line L36 (12.8413, -28.2232) -> (1.0236, -26.1394)
  line L37 (-13.2059, -175.9444) -> (12.8413, -28.2232)
  line L38 (-25.0236, -173.8606) -> (-13.2059, -175.9444)
  line L39 (-33.706, -223.101) -> (-25.0236, -173.8606)
  line L40 (-21.8883, -225.1847) -> (-33.706, -223.101)
  line L41 (-43.5944, -348.2857) -> (-21.8883, -225.1847)
  line L42 (-55.412, -346.2019) -> (-43.5944, -348.2857)
  line L43 (-142.5649, -369.6559) -> (-55.412, -346.2019)
  line L44 (-141.0057, -375.4498) -> (-142.5649, -369.6559)
  line L45 (-131.3492, -372.8511) -> (-141.0057, -375.4498)
  line L46 (-129.79, -378.645) -> (-131.3492, -372.8511)
  line L47 (-207.0416, -399.4344) -> (-129.79, -378.645)
  line L48 (-208.6008, -393.6405) -> (-207.0416, -399.4344)
  line L49 (-198.9443, -391.0418) -> (-208.6008, -393.6405)
  line L50 (-200.5035, -385.248) -> (-198.9443, -391.0418)
  line L51 (-287.6564, -408.7019) -> (-200.5035, -385.248)
  line L52 (-287.6564, -477.4519) -> (-287.6564, -408.7019)
  line L53 (-299.6564, -477.4519) -> (-287.6564, -477.4519)
  line L54 (-299.6564, -527.4519) -> (-299.6564, -477.4519)
  line L55 (-287.6564, -527.4519) -> (-299.6564, -527.4519)
  line L56 (-287.6564, -584.2019) -> (-287.6564, -527.4519)
  line L57 (-193.6564, -584.2019) -> (-287.6564, -584.2019)
  line L58 (-193.6564, -596.2019) -> (-193.6564, -584.2019)
  line L59 (-143.6564, -596.2019) -> (-193.6564, -596.2019)
  line L60 (-143.6564, -584.2019) -> (-143.6564, -596.2019)
  line L61 (-18.6564, -584.2019) -> (-143.6564, -584.2019)
  line L62 (-18.6564, -596.2019) -> (-18.6564, -584.2019)
  line L63 (31.3436, -596.2019) -> (-18.6564, -596.2019)
  line L64 (31.3436, -584.2019) -> (31.3436, -596.2019)
  line L65 (156.3436, -584.2019) -> (31.3436, -584.2019)
  line L66 (23.4999, 389.2686) -> (142.9218, 389.2686)
  line L67 (23.4999, 377.2686) -> (23.4999, 389.2686)
  line L68 (142.9218, 377.2686) -> (23.4999, 377.2686)
  line L69 (142.9218, 389.2686) -> (142.9218, 377.2686)
  line L70 (192.9218, 389.2686) -> (312.3436, 389.2686)
  line L71 (192.9218, 377.2686) -> (192.9218, 389.2686)
  line L72 (312.3436, 377.2686) -> (192.9218, 377.2686)
  line L73 (312.3436, 389.2686) -> (312.3436, 377.2686)
  line L74 (300.3436, 377.2686) -> (312.3436, 377.2686)
  line L75 (300.3436, 171.5333) -> (300.3436, 377.2686)
  line L76 (312.3436, 171.5333) -> (300.3436, 171.5333)
  line L77 (312.3436, 377.2686) -> (312.3436, 171.5333)
  line L78 (56.2534, 217.9787) -> (44.4357, 220.0625)
  line L79 (77.9594, 341.0797) -> (56.2534, 217.9787)
  line L80 (66.1417, 343.1635) -> (77.9594, 341.0797)
  line L81 (64.0579, 331.3458) -> (66.1417, 343.1635)
  line L82 (44.4357, 220.0625) -> (64.0579, 331.3458)
  line L83 (21.5237, 21.0172) -> (47.5709, 168.7384)
  line L84 (35.7532, 170.8221) -> (47.5709, 168.7384)
  line L85 (9.706, 23.101) -> (35.7532, 170.8221)
  line L86 (21.5237, 21.0172) -> (9.706, 23.101)
  line L87 (47.5709, 168.7384) -> (21.5237, 21.0172)
  line L88 (300.3436, 121.5333) -> (300.3436, -78.4667)
  line L89 (312.3436, -78.4667) -> (312.3436, 121.5333)
  line L90 (-25.0236, -173.8606) -> (1.0236, -26.1394)
  line L91 (-55.4008, -346.1384) -> (-33.706, -223.101)
  line L92 (1.0236, -26.1394) -> (12.8413, -28.2232)
  line L93 (-25.0236, -173.8606) -> (1.0236, -26.1394)
  line L94 (-13.2059, -175.9444) -> (-25.0236, -173.8606)
  line L95 (12.8413, -28.2232) -> (-13.2059, -175.9444)
  line L96 (-33.706, -223.101) -> (-21.8883, -225.1847)
  line L97 (-55.4008, -346.1384) -> (-33.706, -223.101)
  line L98 (-43.5831, -348.2221) -> (-55.4008, -346.1384)
  line L99 (-21.8883, -225.1847) -> (-43.5831, -348.2221)
  line L100 (-142.5649, -369.6559) -> (-141.0057, -375.4498)
  line L101 (-200.5035, -385.248) -> (-142.5649, -369.6559)
  line L102 (-198.9443, -391.0418) -> (-200.5035, -385.248)
  line L103 (-208.6008, -393.6405) -> (-198.9443, -391.0418)
  line L104 (-207.0416, -399.4344) -> (-208.6008, -393.6405)
  line L105 (-129.79, -378.645) -> (-207.0416, -399.4344)
  line L106 (-131.3492, -372.8511) -> (-129.79, -378.645)
  line L107 (-141.0057, -375.4498) -> (-131.3492, -372.8511)
  line L108 (-287.6564, -477.4519) -> (-299.6564, -477.4519)
  line L109 (-287.6564, -408.7019) -> (-287.6564, -477.4519)
  line L110 (-299.6564, -408.7019) -> (-287.6564, -408.7019)
  line L111 (-299.6564, -477.4519) -> (-299.6564, -408.7019)
  line L112 (-287.6564, -584.2019) -> (-299.6564, -584.2019)
  line L113 (-287.6564, -527.4519) -> (-287.6564, -584.2019)
  line L114 (-299.6564, -527.4519) -> (-287.6564, -527.4519)
  line L115 (-299.6564, -584.2019) -> (-299.6564, -527.4519)
  line L116 (312.3436, -596.2019) -> (-299.6564, -596.2019)
  line L117 (312.3436, -584.2019) -> (312.3436, -596.2019)
  line L118 (-299.6564, -584.2019) -> (312.3436, -584.2019)
  line L119 (-299.6564, -596.2019) -> (-299.6564, -584.2019)
  line L120 (300.3436, -378.4667) -> (312.3436, -378.4667)
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sketch "Sketch9" plane through (0, 381.5494, -67.2775) normal (0, 0.9848, -0.1736) x axis (-1, 0, 0)
  line L1 (300, 56.4529) -> (300, 44.4529)
  line L2 (288, 56.4529) -> (300, 56.4529)
  line L3 (288, 44.4529) -> (288, 56.4529)
  line L4 (300, 44.4529) -> (288, 44.4529)
  line L5 (-212, 56.4529) -> (-212, 44.4529)
  line L6 (-224, 56.4529) -> (-212, 56.4529)
  line L7 (-224, 44.4529) -> (-224, 56.4529)
  line L8 (-212, 44.4529) -> (-224, 44.4529)
  line L9 (-224, 56.4529) -> (300, 56.4529)
  line L10 (-224, 44.4529) -> (-224, 56.4529)
  line L11 (300, 44.4529) -> (-224, 44.4529)
  line L12 (300, 56.4529) -> (300, 44.4529)
  point P9 (-224, 44.4529)
  point P12 (-224, 44.4529)
  point P3 (300, 56.4529)
  point P10 (300, 56.4529)
  horizontal L9
  vertical L10
  horizontal L11
  vertical L12
  coincident P9 P12
  coincident P3 P10
extrude "Extrude1" new body sketch "Sketch9" profile of L3 L5 L9 L11 to an object
sketch "Sketch10" plane through (0, 9.8029, 55.5952) normal (0, 0.1736, 0.9848) x axis (1, 0, 0)
  line L1 (-288, 337.4354) -> (-288, 349.4354)
  line L2 (212, 337.4354) -> (-288, 337.4354)
  line L3 (212, 349.4354) -> (212, 337.4354)
  line L4 (-288, 349.4354) -> (212, 349.4354)
sketch "Sketch11" plane through (0, 344.1267, -60.6788) normal (0, 0.9848, -0.1736) x axis (-1, 0, 0)
  line L1 (-212, 56.4529) -> (288, 56.4529)
  line L2 (-212, -5.5471) -> (-212, 56.4529)
  line L3 (-127, -5.5471) -> (-212, -5.5471)
  line L4 (-127, -17.5471) -> (-127, -5.5471)
  line L5 (-77, -17.5471) -> (-127, -17.5471)
  line L6 (-77, -5.5471) -> (-77, -17.5471)
  line L7 (13, -5.5471) -> (-77, -5.5471)
  line L8 (13, -17.5471) -> (13, -5.5471)
  line L9 (63, -17.5471) -> (13, -17.5471)
  line L10 (63, -5.5471) -> (63, -17.5471)
  line L11 (153, -5.5471) -> (63, -5.5471)
  line L12 (153, -17.5471) -> (153, -5.5471)
  line L13 (203, -17.5471) -> (153, -17.5471)
  line L14 (203, -5.5471) -> (203, -17.5471)
  line L15 (288, -5.5471) -> (203, -5.5471)
  line L16 (288, 56.4529) -> (288, -5.5471)
  line L17 (288, 56.4529) -> (-212, 56.4529)
  line L18 (288, 44.4529) -> (288, 56.4529)
  line L19 (-212, 44.4529) -> (288, 44.4529)
  line L20 (-212, 56.4529) -> (-212, 44.4529)
  line L21 (38, 44.4529) -> (38, 56.4529)
  line L22 (-2, 44.4529) -> (-2, 56.4529)
  line L23 (13, 44.4529) -> (13, 56.4529)
  line L24 (78, 44.4529) -> (78, 56.4529)
  line L25 (63, 44.4529) -> (63, 56.4529)
  line L26 (-152, 44.4529) -> (-152, 56.4529)
  line L27 (-137, 44.4529) -> (-137, 56.4529)
  line L28 (-87, 44.4529) -> (-87, 56.4529)
  line L29 (-72, 44.4529) -> (-72, 56.4529)
  line L30 (148, 44.4529) -> (148, 56.4529)
  line L31 (163, 44.4529) -> (163, 56.4529)
  line L32 (213, 44.4529) -> (213, 56.4529)
  line L33 (228, 44.4529) -> (228, 56.4529)
  line L34 (288, 50.4529) -> (-212, 50.4529)
  point P20 (288, 44.4529)
  point P22 (288, 44.4529)
  point P3 (-212, 56.4529)
  point P18 (-212, 56.4529)
  point P23 (38, 56.4529)
  point P24 (38, 44.4529)
  horizontal L17
  vertical L18
  horizontal L19
  vertical L20
  coincident P20 P22
  coincident P3 P18
  midpoint L1 P23
  midpoint L19 P24
  dimension "d53" = 40
  dimension "d54" = 25
  dimension "d55" = -40
  dimension "d56" = -25
  dimension "d61" = 6 (= "th / 2")
  dimension "d59" R-Pattern1-uDistance = 150
  dimension "d60" R-Pattern1-vDistance = 0
extrude "Extrude3" cut sketch "Sketch11" profile of L1 L17 L19 L21 L22 L23 L24 L25 L26 L27 L28 L29 L30 L31 L32 L33 L34 to an object
combine "Combine1"
position "Position6"
position "Position7"
sketch "Sketch12" plane through (-300, 0, 0) normal (-1, 0, 0) x axis (0, 0, 1)
  line L1 (-142.9218, 389.2686) -> (-142.9218, 377.2686)
  line L2 (-192.9218, 389.2686) -> (-142.9218, 389.2686)
  line L3 (-192.9218, 377.2686) -> (-192.9218, 389.2686)
  line L4 (-300.3436, 377.2686) -> (-192.9218, 377.2686)
  line L5 (-300.3436, 171.5333) -> (-300.3436, 377.2686)
  line L6 (-312.3436, 171.5333) -> (-300.3436, 171.5333)
  line L7 (-312.3436, 121.5333) -> (-312.3436, 171.5333)
  line L8 (-300.3436, 121.5333) -> (-312.3436, 121.5333)
  line L9 (-300.3436, -78.4667) -> (-300.3436, 121.5333)
  line L10 (-312.3436, -78.4667) -> (-300.3436, -78.4667)
  line L11 (-312.3436, -128.4667) -> (-312.3436, -78.4667)
  line L12 (-300.3436, -128.4667) -> (-312.3436, -128.4667)
  line L13 (-300.3436, -328.4667) -> (-300.3436, -128.4667)
  line L14 (-312.3436, -328.4667) -> (-300.3436, -328.4667)
  line L15 (-312.3436, -378.4667) -> (-312.3436, -328.4667)
  line L16 (-300.3436, -378.4667) -> (-312.3436, -378.4667)
  line L17 (-300.3436, -584.2019) -> (-300.3436, -378.4667)
  line L18 (-206.3436, -584.2019) -> (-300.3436, -584.2019)
  line L19 (-206.3436, -596.2019) -> (-206.3436, -584.2019)
  line L20 (-156.3436, -596.2019) -> (-206.3436, -596.2019)
  line L21 (-156.3436, -584.2019) -> (-156.3436, -596.2019)
  line L22 (-31.3436, -584.2019) -> (-156.3436, -584.2019)
  line L23 (-31.3436, -596.2019) -> (-31.3436, -584.2019)
  line L24 (18.6564, -596.2019) -> (-31.3436, -596.2019)
  line L25 (18.6564, -584.2019) -> (18.6564, -596.2019)
  line L26 (143.6564, -584.2019) -> (18.6564, -584.2019)
  line L27 (143.6564, -596.2019) -> (143.6564, -584.2019)
  line L28 (193.6564, -596.2019) -> (143.6564, -596.2019)
  line L29 (193.6564, -584.2019) -> (193.6564, -596.2019)
  line L30 (287.6564, -584.2019) -> (193.6564, -584.2019)
  line L31 (287.6564, -527.4519) -> (287.6564, -584.2019)
  line L32 (299.6564, -527.4519) -> (287.6564, -527.4519)
  line L33 (299.6564, -477.4519) -> (299.6564, -527.4519)
  line L34 (287.6564, -477.4519) -> (299.6564, -477.4519)
  line L35 (287.6564, -408.7019) -> (287.6564, -477.4519)
  line L36 (200.5035, -385.248) -> (287.6564, -408.7019)
  line L37 (198.9443, -391.0418) -> (200.5035, -385.248)
  line L38 (208.6008, -393.6405) -> (198.9443, -391.0418)
  line L39 (207.0416, -399.4344) -> (208.6008, -393.6405)
  line L40 (129.79, -378.645) -> (207.0416, -399.4344)
  line L41 (131.3492, -372.8511) -> (129.79, -378.645)
  line L42 (141.0057, -375.4498) -> (131.3492, -372.8511)
  line L43 (142.5649, -369.6559) -> (141.0057, -375.4498)
  line L44 (55.412, -346.2019) -> (142.5649, -369.6559)
  line L45 (43.5944, -348.2857) -> (55.412, -346.2019)
  line L46 (21.8883, -225.1847) -> (43.5944, -348.2857)
  line L47 (33.706, -223.101) -> (21.8883, -225.1847)
  line L48 (25.0236, -173.8606) -> (33.706, -223.101)
  line L49 (13.2059, -175.9444) -> (25.0236, -173.8606)
  line L50 (-12.8413, -28.2232) -> (13.2059, -175.9444)
  line L51 (-1.0236, -26.1394) -> (-12.8413, -28.2232)
  line L52 (-9.706, 23.101) -> (-1.0236, -26.1394)
  line L53 (-21.5237, 21.0172) -> (-9.706, 23.101)
  line L54 (-47.5709, 168.7384) -> (-21.5237, 21.0172)
  line L55 (-35.7532, 170.8221) -> (-47.5709, 168.7384)
  line L56 (-44.4357, 220.0625) -> (-35.7532, 170.8221)
  line L57 (-56.2534, 217.9787) -> (-44.4357, 220.0625)
  line L58 (-77.9594, 341.0797) -> (-56.2534, 217.9787)
  line L59 (-66.1417, 343.1635) -> (-77.9594, 341.0797)
  line L60 (-64.0579, 331.3458) -> (-66.1417, 343.1635)
  line L61 (-2.9998, 342.112) -> (-64.0579, 331.3458)
  line L62 (-11.6822, 391.3524) -> (-2.9998, 342.112)
  line L63 (-23.4999, 389.2686) -> (-11.6822, 391.3524)
  line L64 (-23.4999, 377.2686) -> (-23.4999, 389.2686)
  line L65 (-142.9218, 377.2686) -> (-23.4999, 377.2686)
  line L66 (-207.9218, 389.2686) -> (-192.9218, 389.2686)
  line L67 (-207.9218, 377.2686) -> (-207.9218, 389.2686)
  line L68 (-192.9218, 377.2686) -> (-207.9218, 377.2686)
  line L69 (-192.9218, 389.2686) -> (-192.9218, 377.2686)
  line L70 (-142.9218, 389.2686) -> (-127.9218, 389.2686)
  line L71 (-142.9218, 377.2686) -> (-142.9218, 389.2686)
  line L72 (-127.9218, 377.2686) -> (-142.9218, 377.2686)
  line L73 (-127.9218, 389.2686) -> (-127.9218, 377.2686)
  line L74 (-312.3436, 171.5333) -> (-312.3436, 186.5333)
  line L75 (-300.3436, 171.5333) -> (-312.3436, 171.5333)
  line L76 (-300.3436, 186.5333) -> (-300.3436, 171.5333)
  line L77 (-312.3436, 186.5333) -> (-300.3436, 186.5333)
  line L78 (-312.3436, 106.5333) -> (-312.3436, 121.5333)
  line L79 (-300.3436, 106.5333) -> (-312.3436, 106.5333)
  line L80 (-300.3436, 121.5333) -> (-300.3436, 106.5333)
  line L81 (-312.3436, 121.5333) -> (-300.3436, 121.5333)
  line L82 (-312.3436, -78.4667) -> (-312.3436, -63.4667)
  line L83 (-300.3436, -78.4667) -> (-312.3436, -78.4667)
  line L84 (-300.3436, -63.4667) -> (-300.3436, -78.4667)
  line L85 (-312.3436, -63.4667) -> (-300.3436, -63.4667)
  line L86 (-312.3436, -143.4667) -> (-312.3436, -128.4667)
  line L87 (-300.3436, -143.4667) -> (-312.3436, -143.4667)
  line L88 (-300.3436, -128.4667) -> (-300.3436, -143.4667)
  line L89 (-312.3436, -128.4667) -> (-300.3436, -128.4667)
  line L90 (-312.3436, -328.4667) -> (-312.3436, -313.4667)
  line L91 (-300.3436, -328.4667) -> (-312.3436, -328.4667)
  line L92 (-300.3436, -313.4667) -> (-300.3436, -328.4667)
  line L93 (-312.3436, -313.4667) -> (-300.3436, -313.4667)
  line L94 (-312.3436, -393.4667) -> (-312.3436, -378.4667)
  line L95 (-300.3436, -393.4667) -> (-312.3436, -393.4667)
  line L96 (-300.3436, -378.4667) -> (-300.3436, -393.4667)
  line L97 (-312.3436, -378.4667) -> (-300.3436, -378.4667)
  line L98 (-141.3436, -596.2019) -> (-156.3436, -596.2019)
  line L99 (-141.3436, -584.2019) -> (-141.3436, -596.2019)
  line L100 (-156.3436, -584.2019) -> (-141.3436, -584.2019)
  line L101 (-156.3436, -596.2019) -> (-156.3436, -584.2019)
  line L102 (-206.3436, -596.2019) -> (-221.3436, -596.2019)
  line L103 (-206.3436, -584.2019) -> (-206.3436, -596.2019)
  line L104 (-221.3436, -584.2019) -> (-206.3436, -584.2019)
  line L105 (-221.3436, -596.2019) -> (-221.3436, -584.2019)
  line L106 (-31.3436, -596.2019) -> (-46.3436, -596.2019)
  line L107 (-31.3436, -584.2019) -> (-31.3436, -596.2019)
  line L108 (-46.3436, -584.2019) -> (-31.3436, -584.2019)
  line L109 (-46.3436, -596.2019) -> (-46.3436, -584.2019)
  line L110 (33.6564, -596.2019) -> (18.6564, -596.2019)
  line L111 (33.6564, -584.2019) -> (33.6564, -596.2019)
  line L112 (18.6564, -584.2019) -> (33.6564, -584.2019)
  line L113 (18.6564, -596.2019) -> (18.6564, -584.2019)
  line L114 (287.6564, -477.4519) -> (287.6564, -452.4519)
  line L115 (299.6564, -477.4519) -> (287.6564, -477.4519)
  line L116 (299.6564, -452.4519) -> (299.6564, -477.4519)
  line L117 (287.6564, -452.4519) -> (299.6564, -452.4519)
  line L118 (287.6564, -552.4519) -> (287.6564, -527.4519)
  line L119 (299.6564, -552.4519) -> (287.6564, -552.4519)
  line L120 (299.6564, -527.4519) -> (299.6564, -552.4519)
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extrude "Extrude1" new body sketch "Sketch12" no distance stored
combine "Combine1"
extrude "Extrude1" new body sketch "Sketch13" no distance stored
combine "Combine1"
combine "Combine1"
extrude "Extrude2" cut of existing geometry blind -1
offset_faces "OffsetFaces1" distance 12 (= "th")
offset_faces "OffsetFaces1" distance 12 (= "th")
combine "Combine2"
combine "Combine2"
extrude "Extrude3" cut of existing geometry blind -1
component_insert "Component Insert2"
